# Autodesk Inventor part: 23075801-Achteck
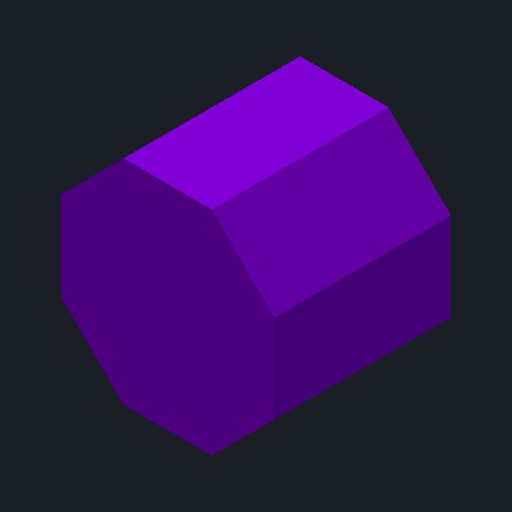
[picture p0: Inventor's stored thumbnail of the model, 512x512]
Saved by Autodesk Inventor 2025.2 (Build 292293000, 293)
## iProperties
Company: Ed. Züblin AG
Created: 2025-03
Part Number: 23075801-Achteck
Material: Stahlbeton C30/37
Document SubType Name: Modeling
Designer: FrodlSte
Mass: 3.01777e+06 g
Surface Area: 64142.1 cm^2
Volume: 1.20711e+06 cm^3
Density: 2.5 g/cm^3
Appearance: Beton C30/37
Description: Zwickel
z_Bereich: Tunnelbau
z_Direktion: Tief- und Tunnelbau
z_Konzerneinheit: Zentrale Technik
z_Matchkey: =<z_Matchkey_010>_<z_Matchkey_020>_<z_Matchkey_030>_<z_Matchkey_040>_<z_Matchkey_050>_<z_Matchkey_060>_<z_Matchkey_070>_<z_Matchkey_080>_<z_Matchkey_090>_<z_Mat
cpiComponentType: Attribut
cpiFitMatchkey: =<z_Matchkey>
z_Matchkey_010: xxxxx
z_Matchkey_020: 5DTUB
z_Matchkey_030: xxx
z_Matchkey_040: xxx
z_Matchkey_050: xxx
z_Matchkey_060: xxx
z_Matchkey_070: xxx
z_Matchkey_080: xxx
z_Matchkey_090: xxx
z_Matchkey_100: xxx
z_Matchkey_110: xxx
z_Matchkey_120: xxxxxxx
z_Matchkey_130: xxxx
z_Matchkey_140: xxxx
DocNumber: 23075801-Achteck.ipt
Folder: DL23075801-DE-Pfaffensteigtunnel\BIM\Testmodell
VDS_Category: 09 - BIM - Konstruktion
DBSet_Beton:Betondeckung_mm: -9999,900000000001
DBSet_Beton:Betonstahlguete: BST_500A
DBSet_Beton:Bewehrungsgehalt: -99999.0
DBSet_Beton:Druckfestigkeitsklasse: C12/15
DBSet_Beton:Expositionsklasse_X: ND
DBSet_Beton:Expositionsklasse_XA: ND
DBSet_Beton:Expositionsklasse_XC: ND
DBSet_Beton:Expositionsklasse_XD: ND
DBSet_Beton:Expositionsklasse_XF: ND
DBSet_Beton:Expositionsklasse_XM: ND
DBSet_Beton:Expositionsklasse_XS: ND
DBSet_Beton:Feuchtigkeitsklasse: ND
DBSet_Beton:Groesstkorn: 11
DBSet_Beton:Herstellungsort: FTB
DBSet_Beton:Luftporenbeton: ND
DBSet_Beton:PP_Faser: False
DBSet_Beton:PP_Faser_Gehalt: -99999.0
DBSet_Beton:Rohdichte: -99999.0
DBSet_Beton:Sichtbetonklasse: ND
DBSet_Beton:Unbewehrter_Beton: False
DBSet_Beton:Wasserzementwert_max: -99999.0
DBSet_Beton:WU_Beton: False
DBSet_Beton:Zusatzmittel: ND
DBSet_Element:010_Eigentuemer: DBE
DBSet_Element:020_Autor: ND
DBSet_Element:030_Projektnummer: G.016268527
DBSet_Element:040_Bereich: ND
DBSet_Element:050_Vertragspartner: ND
DBSet_Element:060_Gewerk: ND
DBSet_Element:070_Bauwerk: EW
DBSet_Element:080_Bauwerksnummer: 17030
DBSet_Element:090_Bezeichnung: ND
DBSet_Element:100_Gruppe: Aussenschale
DBSet_Element:110_Element: ND
DBSet_Element:120_Elementtyp: ND
DBSet_Element:130_Identifikationsnummer: ND
DBSet_Element:140_Position_1: KALO
DBSet_Element:150_Position_2: FIRS
DBSet_Element:160_PUID: ND
DBSet_Element:170_Hauptmaterialitaet: ND
DBSet_Element:171_Materialindikator_1: ND
DBSet_Element:172_Materialindikator_2: ND
DBSet_Geometrie:Aussenflaeche: -99999.0
DBSet_Geometrie:Dicke: -99999.0
DBSet_Geometrie:Laenge: -99999.0
DBSet_Geometrie:Volumen_Solid: 7.21
DBSet_Position:Streckenachse: ND
DBSet_Position:Streckenkilometer_Anfang: -99999
DBSet_Position:Streckenkilometer_Ende: -99999
DBSet_Position:Tunnelachse: ND
DBSet_Position:Tunnelmeter_Anfang: -99999
DBSet_Position:Tunnelmeter_Ende: -99999
DBSet_TP:Status: ABB
z_DBSet_Beton:Betondeckung_mm: -99999,000 mm
z_DBSet_Beton:Betonstahlguete: BST_500A
z_DBSet_Beton:Bewehrungsgehalt: -99999,000 oE
z_DBSet_Beton:Druckfestigkeitsklasse: Beton C25/30
z_DBSet_Beton:Expositionsklasse_X: Nicht definiert
z_DBSet_Beton:Expositionsklasse_XA: Nicht definiert
z_DBSet_Beton:Expositionsklasse_XC: Nicht definiert
z_DBSet_Beton:Expositionsklasse_XD: Nicht definiert
z_DBSet_Beton:Expositionsklasse_XF: Nicht definiert
z_DBSet_Beton:Expositionsklasse_XM: Nicht definiert
z_DBSet_Beton:Expositionsklasse_XS: Nicht definiert
z_DBSet_Beton:Feuchtigkeitsklasse: Nicht definiert
z_DBSet_Beton:Groesstkorn: 8 mm
z_DBSet_Beton:Herstellungsort: Spritzbeton
z_DBSet_Beton:Luftporenbeton: nicht definiert
z_DBSet_Beton:PP_Faser: Falsch
z_DBSet_Beton:PP_Faser_Gehalt: -99999,000 oE
z_DBSet_Beton:Rohdichte: -99999,000 oE
z_DBSet_Beton:Sichtbetonklasse: Nicht definiert
z_DBSet_Beton:Unbewehrter_Beton: Falsch
z_DBSet_Beton:Wasserzementwert_max: -99999,000 oE
z_DBSet_Beton:WU_Beton: Falsch
z_DBSet_Beton:Zusatzmittel: nicht definiert
z_DBSet_Element:010_Eigentuemer: DBInfraGo
z_DBSet_Element:020_Autor: Vertragspartner 2 ZB
z_DBSet_Element:030_Projektnummer: Gaeubahn Nord HP Goldberg (DBnfraGO, BK11)
z_DBSet_Element:040_Bereich: PFA 1 Tunnel
z_DBSet_Element:050_Vertragspartner: Tunnel
z_DBSet_Element:060_Gewerk: Tunnelbau
z_DBSet_Element:070_Bauwerk: SBW-Tu
z_DBSet_Element:080_Bauwerksnummer: zzz (leer)
z_DBSet_Element:090_Bezeichnung: zzz (leer)
z_DBSet_Element:100_Gruppe: Aussenschale
z_DBSet_Element:110_Element: Zwickel
z_DBSet_Element:120_Elementtyp: Spiess
z_DBSet_Element:130_Identifikationsnummer: nicht definiert
z_DBSet_Element:140_Position_1: Kalotte
z_DBSet_Element:150_Position_2: Firste
z_DBSet_Element:160_PUID: nicht definiert
z_DBSet_Element:170_Hauptmaterialitaet: nicht definiert
z_DBSet_Element:171_Materialindikator_1: nicht definiert
z_DBSet_Element:172_Materialindikator_2: nicht definiert
z_DBSet_Geometrie:Aussenflaeche: -99999,000 m^2
z_DBSet_Geometrie:Dicke: -99999,000 m
z_DBSet_Geometrie:Laenge: -99999,000 m
z_DBSet_Position:Streckenachse: zzz (leer)
z_DBSet_Position:Streckenkilometer_Anfang: -11111,000 oE
z_DBSet_Position:Streckenkilometer_Ende: -11111,000 oE
z_DBSet_Position:Tunnelachse: zzz (leer)
z_DBSet_Position:Tunnelmeter_Anfang: -11111,000 oE
z_DBSet_Position:Tunnelmeter_Ende: -11111,000 oE
z_DBSet_TP:Status: Neubau
z_DBSet_Geometrie:Volumen_Solid: -11111,000 m^3
Author: FrodlSte
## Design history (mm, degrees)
derived "23075801-Skelett.ipt"
node "Achteck"
node "Volumenkörpern"
node "Oberflächenkörpern"
feature "Achteck::23075801-Skelett.ipt" dims "d4" = 10
tag "Bezeichnung1"
